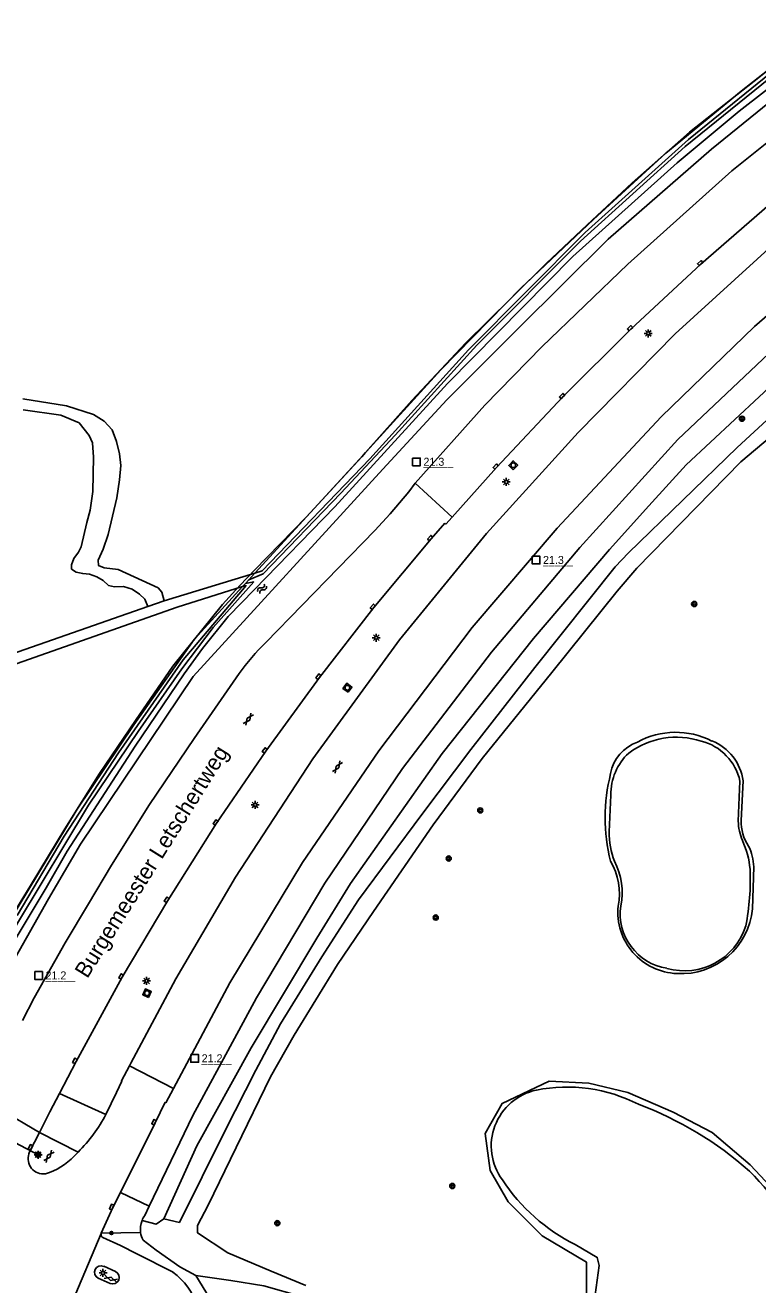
# Model space of a CAD drawing. Extents: x 124000 to 129000, y 395500 to 397503.
# Drawn here: x 124828 to 124942.4, y 396885.3 to 397082 of the extents above; entities that cross this region are included whole.
import ezdxf

# ---------------------------------------------------------------- set-up
doc = ezdxf.new("R2010")
doc.units = 0
for name, color, linetype in [('gg-afsc-draadraster', 7, 'Continuous'), ('gg-afsc-erfafscheiding', 7, 'Continuous'), ('gg-afsc-lijn draadraster', 7, 'Continuous'), ('gg-anno-openbare ruimte label', 7, 'Continuous'), ('gg-knt-bovenkant onderkant talud', 7, 'Continuous'), ('gg-knt-verharding', 7, 'Continuous'), ('gg-knt-verharding nz', 7, 'Continuous'), ('gg-kntw-bovenkant insteek waterloop', 7, 'Continuous'), ('gg-kntw-waterlijn', 7, 'Continuous'), ('gt-anno-nummer hm paal', 7, 'Continuous'), ('gt-grn-groengrens', 7, 'Continuous'), ('gt-grn-vlakafsluiter', 7, 'Continuous'), ('gt-grn-weggrens', 7, 'Continuous'), ('gt-grn-weggrens revisie', 7, 'Continuous'), ('gt-knt-lijn portaal', 7, 'Continuous'), ('gt-symb-boom', 7, 'Continuous'), ('gt-symb-gesloten verharding', 7, 'Continuous'), ('gt-symb-hm paal', 7, 'Continuous'), ('gt-symb-kolk', 7, 'Continuous'), ('gt-symb-lichtmast', 7, 'Continuous'), ('gt-symb-portaalmast', 7, 'Continuous'), ('gt-symb-rioolschacht', 7, 'Continuous'), ('gt-symb-verkeersregelinstallatiepaal', 7, 'Continuous'), ('gt-symb-watersymbool', 7, 'Continuous'), ('gx-grn-maaiveld', 7, 'Continuous')]:
    doc.layers.add(name, color=color, linetype=linetype)

# ---------------------------------------------------------------- blocks, each defined once
blk = doc.blocks.new('gt0-KOLK')
at = {"layer": 'gt-symb-kolk'}
blk.add_lwpolyline([(0, 0), (0.38, 0), (0.38, 0.4), (-0.38, 0.4), (-0.38, 0), (0, 0)], dxfattribs=at)
blk = doc.blocks.new('gt0-WA')
at = {"layer": 'gt-symb-watersymbool'}
for centre, start, end in [((-0.32, 0.02), 28.0725, 151.9275), ((0.43, 0.42), 208.0725, 331.9275), ((-0.32, -0.43), 28.0725, 151.9275), ((0.43, -0.03), 208.0725, 331.9275)]:
    blk.add_arc(centre, 0.425, start, end, dxfattribs=at)
blk = doc.blocks.new('gt0-LMAST')
at = {"layer": 'gt-symb-lichtmast'}
for p, q in [((-0.18, 0.17), (-0.45, 0.44)), ((-0.01, 0.25), (-0.01, 0.62)), ((0.17, 0.17), (0.44, 0.44)), ((-0.26, 0), (-0.63, 0)), ((-0.18, -0.18), (-0.45, -0.45)), ((-0.01, -0.25), (-0.01, -0.63)), ((0.44, -0.45), (0.17, -0.18)), ((0.24, 0), (0.62, 0))]:
    blk.add_line(p, q, dxfattribs=at)
blk.add_circle((-0.01, 0), 0.25, dxfattribs=at)
blk = doc.blocks.new('gt0-HMpaal')
at = {"layer": 'gt-symb-hm paal'}
blk.add_lwpolyline([(-0.6, 0.6), (0.6, 0.6), (0.6, -0.6), (-0.6, -0.6)], close=True, dxfattribs=at)
blk = doc.blocks.new('gt0-BOOM')
at = {"layer": 'gt-symb-boom'}
for radius in [0.4, 0.2]:
    blk.add_circle((0, 0), radius, dxfattribs=at)
blk = doc.blocks.new('gt0-RS')
at = {"layer": 'gt-symb-rioolschacht'}
blk.add_lwpolyline([(-0.5, -0.5), (0.5, -0.5), (0.5, 0.5), (-0.5, 0.5)], close=True, dxfattribs=at)
blk.add_circle((0, 0), 0.375, dxfattribs=at)
blk = doc.blocks.new('gt0-GESVH1')
at = {"layer": 'gt-symb-gesloten verharding'}
for p, q in [((-0.99, -0.26), (0.01, 0.24)), ((0.01, -0.26), (-0.99, 0.24)), ((0.01, 0.24), (1.01, -0.26)), ((1.01, 0.24), (0.01, -0.26))]:
    blk.add_line(p, q, dxfattribs=at)
blk = doc.blocks.new('gt0-VIPAAL')
at = {"layer": 'gt-symb-verkeersregelinstallatiepaal'}
blk.add_circle((0, 0), 0.25, dxfattribs=at)
blk = doc.blocks.new('gt0-PORTM')
at = {"layer": 'gt-symb-portaalmast'}
for radius in [0.4, 0.33, 0.27, 0.21, 0.15]:
    blk.add_circle((0, 0), radius, dxfattribs=at)

msp = doc.modelspace()

# ---------------------------------------------------------------- linework, layer by layer
at = {"layer": 'gg-afsc-draadraster'}
msp.add_lwpolyline([(124852.13, 396895.04), (124859.22, 396909.31), (124864.06, 396918.81), (124867.89, 396926.04), (124874.34, 396936.52), (124880.07, 396945.45), (124889.97, 396958.75), (124897.62, 396968.88), (124907.59, 396981.72), (124920.14, 396997.4), (124922.2, 396999.59), (124939.16, 397016.07), (124953.14, 397028.9), (124965.37, 397040.23), (124977.75, 397052.08), (124981.63, 397055.63), (124986.57, 397060.09)], dxfattribs=at)
at = {"layer": 'gg-afsc-erfafscheiding'}
for p, q in [((124862.42, 396994.82), (124862.93, 396995.38)), ((124862.93, 396995.38), (124863.89, 396996.43)), ((124861.96, 396994.33), (124862.42, 396994.82))]:
    msp.add_line(p, q, dxfattribs=at)
for points in [[(124863.89, 396996.43), (124870.24, 397003.34), (124880.79, 397014.85), (124892.91, 397028.18), (124905.48, 397040.96), (124916.74, 397051.68), (124928.04, 397062.01), (124939.82, 397071.69), (124953.79, 397082.68), (124966.16, 397091.55), (124976.71, 397098.85), (124979.62, 397100.35)], [(124824.53, 396940.21), (124825.45, 396941.82), (124836.15, 396959.58), (124845, 396972.76), (124854.4, 396986.1), (124861.96, 396994.33)]]:
    msp.add_lwpolyline(points, dxfattribs=at)
at = {"layer": 'gg-afsc-lijn draadraster'}
msp.add_lwpolyline([(124952.24, 397081.52), (124941.82, 397073.27), (124931.72, 397065.27), (124922.79, 397057.37), (124915.77, 397050.8), (124909.36, 397044.79), (124903.93, 397039.43), (124896.79, 397032.37), (124888.37, 397023.41), (124881.14, 397015.26), (124880.58, 397014.62), (124871.92, 397005.17), (124863.85, 396996.9), (124862.89, 396995.91), (124862.56, 396995.57), (124861.7, 396994.68), (124860.9, 396993.85), (124858.86, 396991.56), (124851.09, 396981.91), (124845.29, 396973.45), (124839.62, 396965.15), (124834.26, 396956.52), (124828.97, 396947.84), (124824.96, 396941.28)], dxfattribs=at)
at = {"layer": 'gg-knt-bovenkant onderkant talud'}
for points in [[(124871.83, 396885.23), (124866.42, 396887.43), (124859.7, 396890.32), (124854.96, 396893.43), (124854.95, 396894.59), (124856.63, 396897.73), (124860.99, 396906.76), (124866.33, 396917.79), (124870.01, 396924.28), (124876.81, 396935.34), (124882.39, 396943.62), (124891.74, 396957.15), (124899.39, 396967.51), (124910.24, 396980.92), (124920.44, 396993.62), (124923.5, 396997.2), (124939.72, 397013.81), (124951.19, 397023.47)], [(124854.66, 396886.77), (124852.21, 396888.1), (124848.5, 396890.73), (124846.44, 396892.3)], [(124947.71, 396851.55), (124936.12, 396857.06), (124924.57, 396863.17), (124919.21, 396866.6), (124912.52, 396869.95), (124905.21, 396873.66), (124899.95, 396875.92), (124888.55, 396877.68), (124879.19, 396880.43), (124871.18, 396883.5), (124865.32, 396885.18), (124860.13, 396885.98), (124854.66, 396886.77)]]:
    msp.add_lwpolyline(points, dxfattribs=at)
for centre, radius, start, end in [((124849.74, 396894), 3.71, 158.5133, 187.8785), ((124849.71, 396893.99), 3.68, 187.7883, 207.3731)]:
    msp.add_arc(centre, radius, start, end, dxfattribs=at)
at = {"layer": 'gg-knt-verharding'}
for p, q in [((124888.93, 397010.49), (124887.94, 397009.14)), ((124844.35, 396919.52), (124844.55, 396919.9)), ((124840.66, 396911.9), (124842.32, 396915.32)), ((124830.28, 396909.12), (124828.74, 396906.07)), ((124830.28, 396909.12), (124836.33, 396906.05)), ((124835.68, 396905.42), (124836.33, 396906.05)), ((124839.93, 396893.37), (124839.92, 396893.35)), ((124842.91, 396891.43), (124840.19, 396892.7)), ((124842.91, 396891.43), (124845.48, 396890.13)), ((124845.48, 396890.13), (124851.12, 396887.29)), ((124842.15, 396887.39), (124840.3, 396888.2)), ((124839.45, 396886.37), (124841.31, 396885.54))]:
    msp.add_line(p, q, dxfattribs=at)
for points in [[(125194.89, 397202.09), (125192.9, 397201.28), (125174.66, 397193.51), (125154.05, 397184.42), (125133.52, 397174.96), (125111.34, 397164.23), (125091.94, 397154.63), (125072.1, 397144.23), (125055.92, 397135.43), (125036.39, 397124.64), (125016.69, 397113.37), (124995.91, 397101.03), (124988.32, 397096.18), (124971.92, 397085.18), (124956.01, 397073.42), (124938.33, 397059.27), (124922.1, 397044.69), (124908.71, 397031.79), (124899.79, 397022.66), (124888.93, 397010.49)], [(124844.55, 396919.9), (124851.56, 396933.09), (124860.89, 396948.99), (124872.93, 396967.43), (124886.49, 396986), (124900.04, 397002.62), (124914.34, 397018.39), (124929.47, 397033.78), (124945.2, 397048.09), (124962.23, 397062.03), (124980.25, 397075.52), (124999.09, 397088.08), (125016.82, 397098.71), (125038.01, 397110.9), (125057.64, 397121.88), (125077.17, 397132.43), (125096.81, 397142.56), (125115.47, 397151.93), (125136.66, 397162.15), (125157.49, 397171.8), (125178.45, 397181.16), (125200.22, 397190.42), (125200.95, 397190.72)], [(125177.36, 397186.33), (125157.23, 397177.43), (125136.43, 397167.85), (125114.72, 397157.38), (125095.14, 397147.65), (125075.37, 397137.49), (125061.88, 397130.13), (125062.07, 397129.73), (125059.91, 397128.56), (125046.74, 397121.35), (125033.61, 397113.97), (125020.66, 397106.52), (125007.51, 397098.81), (124996.87, 397092.29), (124982.06, 397082.68), (124969.68, 397074.03), (124957.74, 397064.99), (124945.44, 397055.02), (124933.51, 397044.7), (124922.59, 397034.53), (124911.98, 397023.94), (124901.62, 397012.94), (124894.67, 397005.18)], [(124986.75, 397070.55), (124973.76, 397061.38), (124957.39, 397048.38), (124941.9, 397034.95), (124927.33, 397020.86), (124911.06, 397003.47), (124897.8, 396987.96), (124883.26, 396968.68), (124871.35, 396951.25), (124860.01, 396932.48), (124851.18, 396915.98)], [(124887.94, 397009.14), (124884.99, 397005.7), (124882.6, 397003.07), (124865.6, 396985.6)], [(124894.67, 397005.18), (124893.7, 397004.09), (124893.52, 397004.22)], [(124893.52, 397004.22), (124891.4, 397001.78), (124882.45, 396991.05), (124873.96, 396980.15), (124865.6, 396968.64), (124857.93, 396957.4), (124850.3, 396945.32), (124843.2, 396933.36), (124835.98, 396920.18), (124833.38, 396915.18)], [(124837.92, 396944.78), (124841.54, 396950.86), (124847.44, 396960.3), (124854.4, 396970.64), (124861.45, 396980.74)], [(124827.61, 396926.61), (124829.47, 396930.12), (124834.29, 396938.69), (124837.92, 396944.78)], [(124842.32, 396915.32), (124843.11, 396917.09), (124843.06, 396917.16), (124844.35, 396919.52)], [(124833.38, 396915.18), (124831.89, 396912.32), (124830.28, 396909.12)], [(124851.18, 396915.98), (124849.98, 396913.75), (124849.89, 396913.81)], [(124849.89, 396913.81), (124848.32, 396910.62), (124842.9, 396899.75)], [(124842.9, 396899.75), (124841.72, 396897.38), (124839.93, 396893.37)]]:
    msp.add_lwpolyline(points, dxfattribs=at)
for centre, radius, start, end in [((124889.29, 396961.18), 34.03, 134.1177, 144.9013), ((124818.18, 396923.98), 25.52, 315.3502, 331.7476), ((124830.87, 396905.01), 2.37, 161.2111, 278.0916), ((124830.85, 396905.02), 2.36, 153.5904, 161.2538), ((124828.67, 396911.8), 9.48, 285.4543, 317.6693), ((124840.39, 396893.16), 0.508, 158.7387, 245.8969), ((124839.88, 396887.28), 1.01, 65.3824, 244.8726), ((124841.71, 396886.48), 1.02, 247.3284, 63.8257), ((124843.95, 396877.9), 11.81, 349.716, 52.6334)]:
    msp.add_arc(centre, radius, start, end, dxfattribs=at)
at = {"layer": 'gg-knt-verharding nz'}
msp.add_line((124839.92, 396893.35), (124835.38, 396882.59), dxfattribs=at)
at = {"layer": 'gg-kntw-bovenkant insteek waterloop'}
for p, q in [((124940.09, 396963.99), (124939.82, 396957.8)), ((124941.76, 396950.58), (124941.58, 396944.04)), ((124825.97, 396935.43), (124831.69, 396945.58)), ((124847.4, 396897.58), (124846.71, 396896.14))]:
    msp.add_line(p, q, dxfattribs=at)
for points in [[(124863.89, 396996.43), (124865.05, 396996.78), (124881.86, 397014.29), (124897.26, 397031.28), (124915.43, 397049.62), (124931.59, 397064.16), (124947.24, 397076.86), (124964.78, 397089.91), (124977.53, 397099.07), (124980.09, 397099.43)], [(124980.38, 397097.3), (124969.08, 397088.94), (124953.29, 397077.33), (124935.15, 397062.63), (124919.02, 397048.6), (124904.94, 397034.59), (124893.87, 397023.51), (124883.85, 397012.68)], [(124981.82, 397058.81), (124980.68, 397060.27), (124979.54, 397059.91), (124959.71, 397044.29), (124945.07, 397031.61), (124929.93, 397017.28), (124914.6, 397000.46), (124900.81, 396984.09), (124886.95, 396965.92), (124874.82, 396948.05), (124864.14, 396930.14), (124854.23, 396911.77), (124847.4, 396897.58)], [(124925.4, 397006.93), (124931.21, 397013.36), (124953.98, 397034.57), (124962.54, 397041.84), (124981.89, 397057.7)], [(124831.69, 396945.58), (124836.7, 396954.12), (124854.28, 396980.32), (124883.85, 397012.68)], [(124849.68, 396895.61), (124854.84, 396906.99), (124863.31, 396922.32), (124873.57, 396939.46), (124878.8, 396947.97), (124893.13, 396968.25), (124907.39, 396986.24), (124919.24, 397000.11), (124925.4, 397006.93)], [(124861.96, 396994.33), (124862.53, 396994.5), (124852.7, 396982.91), (124842.6, 396968.39), (124834.12, 396955.35), (124826.8, 396943)], [(124945.95, 396871.89), (124940.99, 396869.16), (124934.95, 396867.69), (124929.24, 396867.61), (124924.65, 396868.93), (124921.12, 396872.06), (124917.74, 396876.66), (124915.68, 396882.31), (124915.65, 396888.87), (124908.76, 396892.96), (124903.44, 396898.28), (124900.62, 396903.16), (124899.86, 396908.92), (124902.47, 396913.6), (124909.81, 396917.12)], [(124909.81, 396917.12), (124916, 396916.79), (124922.1, 396915.35), (124929.2, 396912.29), (124935.27, 396909.09), (124941.21, 396904.03), (124945.93, 396898.99)], [(124846.28, 396895.36), (124848.51, 396894.79), (124849.68, 396895.61)]]:
    msp.add_lwpolyline(points, dxfattribs=at)
for centre, radius, start, end in [((124929.58, 396959.28), 12.31, 62.6892, 119.0166), ((124925.78, 396963.97), 6.46, 109.6314, 169.6793), ((124932.44, 396963.04), 7.71, 7.0704, 68.7762), ((124946.62, 396958.26), 28.05, 165.8251, 193.9902), ((124946.54, 396957.57), 6.73, 178.0459, 213.8563), ((124934.19, 396950.41), 7.57, 1.3075, 26.7816), ((124910.64, 396946.37), 10.15, 349.1234, 30.2113), ((124930.17, 396943.52), 9.62, 174.4181, 267.5231), ((124930.41, 396945.11), 11.22, 266.6792, 354.5066), ((124849.73, 396894), 3.7, 144.6943, 158.486)]:
    msp.add_arc(centre, radius, start, end, dxfattribs=at)
at = {"layer": 'gg-kntw-waterlijn'}
for p, q in [((124939.34, 396957.72), (124939.6, 396963.95)), ((124919.45, 396961.79), (124919.21, 396956.06))]:
    msp.add_line(p, q, dxfattribs=at)
for points in [[(124952.3, 397078.51), (124939.46, 397068.55), (124929.83, 397060.48), (124913.52, 397045.89), (124893.97, 397026.03), (124876.37, 397006.81), (124863.84, 396993.9), (124859.72, 396989.66), (124855.73, 396984.66), (124852.86, 396980.7), (124845.2, 396969.44), (124834.6, 396953.01), (124831.31, 396947.32), (124825.4, 396937.39), (124823.4, 396933.56)], [(124862.93, 396995.38), (124865.17, 396996.35), (124877.29, 397008.94), (124885.79, 397017.97), (124898.56, 397032.03), (124914.72, 397048.25), (124931.04, 397063.04), (124951.46, 397079.57)], [(124822.74, 396933.91), (124826.84, 396941.8), (124837.94, 396960.23), (124845.66, 396971.72), (124852.49, 396981.52), (124857.38, 396987.97), (124863.72, 396995.07), (124862.42, 396994.82)], [(124916.86, 396882.62), (124917.63, 396888.34), (124917.33, 396889.6), (124913.9, 396891.59)]]:
    msp.add_lwpolyline(points, dxfattribs=at)
for centre, radius, start, end in [((124929.7, 396958.36), 12.46, 71.9447, 126.7468), ((124931.54, 396962.21), 8.25, 12.151, 75.743), ((124928.38, 396961.86), 8.93, 133.3951, 180.4315), ((124931.73, 396955.86), 12.53, 179.0709, 200.622), ((124947.71, 396957.91), 8.37, 181.279, 202.8004), ((124927.59, 396948.96), 13.65, 5.2099, 24.7088), ((124911.18, 396946.65), 10.05, 347.4892, 28.5247), ((124903.78, 396948.63), 37.44, 348.8069, 2.4096), ((124929.55, 396943.27), 8.64, 171.9871, 261.0892), ((124930.94, 396944.39), 10.04, 254.2454, 342.4), ((124909.73, 396906.99), 8.94, 102.2971, 216.2518), ((124912.59, 396891.62), 24.57, 62.975, 101.166), ((124904.37, 396861.84), 55.19, 48.3134, 69.4395), ((124910.25, 396871.72), 43.95, 22.2948, 45.4617), ((124927.18, 396917.99), 29.55, 213.4442, 243.2937)]:
    msp.add_arc(centre, radius, start, end, dxfattribs=at)
at = {"layer": 'gt-grn-groengrens'}
for p, q in [((124840.66, 396911.9), (124833.38, 396915.18)), ((124842.9, 396899.75), (124847.4, 396897.58)), ((124846.06, 396893.49), (124839.93, 396893.37))]:
    msp.add_line(p, q, dxfattribs=at)
at = {"layer": 'gt-grn-vlakafsluiter'}
msp.add_line((124852.13, 396895.04), (124849.68, 396895.61), dxfattribs=at)
msp.add_lwpolyline([(124854.42, 396867.43), (124857.99, 396874.28), (124858.54, 396880.46), (124854.66, 396886.77)], dxfattribs=at)
at = {"layer": 'gt-grn-weggrens'}
msp.add_line((124830.28, 396909.12), (124824.3, 396912.61), dxfattribs=at)
at = {"layer": 'gt-grn-weggrens revisie'}
for p, q in [((124888.93, 397010.49), (124894.67, 397005.18)), ((124851.18, 396915.98), (124844.35, 396919.52))]:
    msp.add_line(p, q, dxfattribs=at)
at = {"layer": 'gt-knt-lijn portaal'}
msp.add_line((124830.06, 396905.62), (124820.6, 396910.58), dxfattribs=at)
at = {"layer": 'gx-grn-maaiveld'}
for p, q in [((124849.74, 396992.13), (124863.89, 396996.43)), ((124847.19, 396991.24), (124849.74, 396992.13))]:
    msp.add_line(p, q, dxfattribs=at)
for points in [[(124849.74, 396992.13), (124849.39, 396993.45), (124848.8, 396994.16), (124842.55, 396997.02), (124840.35, 396997.25), (124839.51, 396997.61), (124839.46, 396998.44), (124840.23, 397000.17), (124841, 397002.49), (124842.34, 397008.19), (124842.79, 397011.01), (124842.95, 397013.23), (124842.79, 397015.04), (124842.28, 397016.97), (124841.61, 397018.81), (124840.39, 397020.16), (124838.71, 397021.21), (124834.47, 397022.55), (124827.67, 397023.64)], [(124827.72, 397021.92), (124833.59, 397021.08), (124836.45, 397019.9), (124838.02, 397017.91), (124838.55, 397016.8), (124838.71, 397014.53), (124838.59, 397009.2), (124838.17, 397006.26), (124837.67, 397004.35), (124836.78, 397000.53), (124836.36, 396999.69), (124835.65, 396998.74), (124835.29, 396997.73), (124835.29, 396997.07), (124836.01, 396996.6), (124837.02, 396996.36), (124838.09, 396996.3), (124839.22, 396995.88), (124840.23, 396995.29), (124841.06, 396994.52), (124842.01, 396994.28), (124843.38, 396994.34), (124844.75, 396993.92), (124845.88, 396993.15), (124846.71, 396992.37), (124847.19, 396991.24)], [(124847.19, 396991.24), (124813.04, 396979.3), (124813.72, 396977.77), (124851.78, 396991.12), (124861.96, 396994.33)]]:
    msp.add_lwpolyline(points, dxfattribs=at)

# ---------------------------------------------------------------- block references
at = {"layer": 'gt-symb-boom'}
for p in [(124939.93, 397020.54), (124932.47, 396991.62), (124899.07, 396959.39), (124894.15, 396951.88), (124892.13, 396942.66), (124894.71, 396900.74), (124867.4, 396894.94)]:
    msp.add_blockref('gt0-BOOM', p, dxfattribs=at)
at = {"layer": 'gt-symb-gesloten verharding'}
for p, rotation in [((124862.87, 396973.63), 54.03584370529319), ((124876.81, 396966.17), -124.32560196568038), ((124831.73, 396905.38), 52.76334102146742), ((124841.41, 396886.26), -17.149043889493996)]:
    msp.add_blockref('gt0-GESVH1', p, dxfattribs=dict(at, rotation=rotation))
at = {"layer": 'gt-symb-hm paal'}
for p in [(124889.12, 397013.81), (124907.79, 396998.48), (124830.14, 396933.61), (124854.5, 396920.66)]:
    msp.add_blockref('gt0-HMpaal', p, dxfattribs=at)
at = {"layer": 'gt-symb-kolk'}
for p, rotation in [((124933.51, 397044.7), 40.86240641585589), ((124922.59, 397034.53), 42.97482613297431), ((124911.98, 397023.94), 44.91895934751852), ((124901.62, 397012.94), 46.70135460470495), ((124891.4, 397001.78), 49.09427391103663), ((124882.45, 396991.05), 50.15042857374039), ((124873.96, 396980.15), 52.109937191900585), ((124865.6, 396968.64), 54.03584370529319), ((124857.93, 396957.4), 55.67439803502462), ((124850.3, 396945.32), 57.70905164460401), ((124843.2, 396933.36), 59.331073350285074), ((124835.98, 396920.18), 61.30721229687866), ((124848.32, 396910.62), 63.51182146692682), ((124829.06, 396906.7), 63.255579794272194), ((124841.72, 396897.38), 65.9211627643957)]:
    msp.add_blockref('gt0-KOLK', p, dxfattribs=dict(at, rotation=rotation))
at = {"layer": 'gt-symb-lichtmast'}
for p in [(124925.29, 397033.87), (124903.14, 397010.68), (124882.84, 396986.36), (124863.94, 396960.26), (124846.99, 396932.78), (124830.06, 396905.62), (124840.2, 396887.17)]:
    msp.add_blockref('gt0-LMAST', p, dxfattribs=at)
at = {"layer": 'gt-symb-portaalmast'}
msp.add_blockref('gt0-PORTM', (124830.06, 396905.62), dxfattribs=at)
at = {"layer": 'gt-symb-rioolschacht'}
for p, rotation in [((124904.22, 397013.28), 45.89137585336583), ((124878.34, 396978.54), 53.74924417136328), ((124847.05, 396930.85), 65.30485348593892)]:
    msp.add_blockref('gt0-RS', p, dxfattribs=dict(at, rotation=rotation))
at = {"layer": 'gt-symb-verkeersregelinstallatiepaal'}
msp.add_blockref('gt0-VIPAAL', (124841.5, 396893.4), dxfattribs=at)
at = {"layer": 'gt-symb-watersymbool', "rotation": 47.63383016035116}
msp.add_blockref('gt0-WA', (124864.98, 396993.95), dxfattribs=at)

# ---------------------------------------------------------------- texts
at = {"layer": 'gg-anno-openbare ruimte label'}
msp.add_text('Burgemeester Letschertweg', height=2.5, rotation=58, dxfattribs=at).set_placement((124837.74, 396933.03))
at = {"layer": 'gt-anno-nummer hm paal'}
for s, p in [('21.3', (124890.21, 397013.2)), ('21.3', (124908.87, 396997.87)), ('21.2', (124831.22, 396933)), ('21.2', (124855.59, 396920.06))]:
    msp.add_text(s, height=1.25, dxfattribs=at).set_placement(p)
at = {"layer": 'gt-symb-hm paal'}
for p in [(124890.21, 397013.2), (124908.87, 396997.87), (124831.22, 396933), (124855.59, 396920.06)]:
    msp.add_text('_____', height=1.25, dxfattribs=at).set_placement(p)

doc.saveas('drawing.dxf')
